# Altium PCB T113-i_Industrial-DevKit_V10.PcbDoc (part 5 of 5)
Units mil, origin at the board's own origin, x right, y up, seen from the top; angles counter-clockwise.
Board outline 4212.61 x 3188.98 mil, 4 copper layers (Top Layer, GND, PWR, Bottom Layer); 249 components, 236 nets, 911 pads, 571 vias.
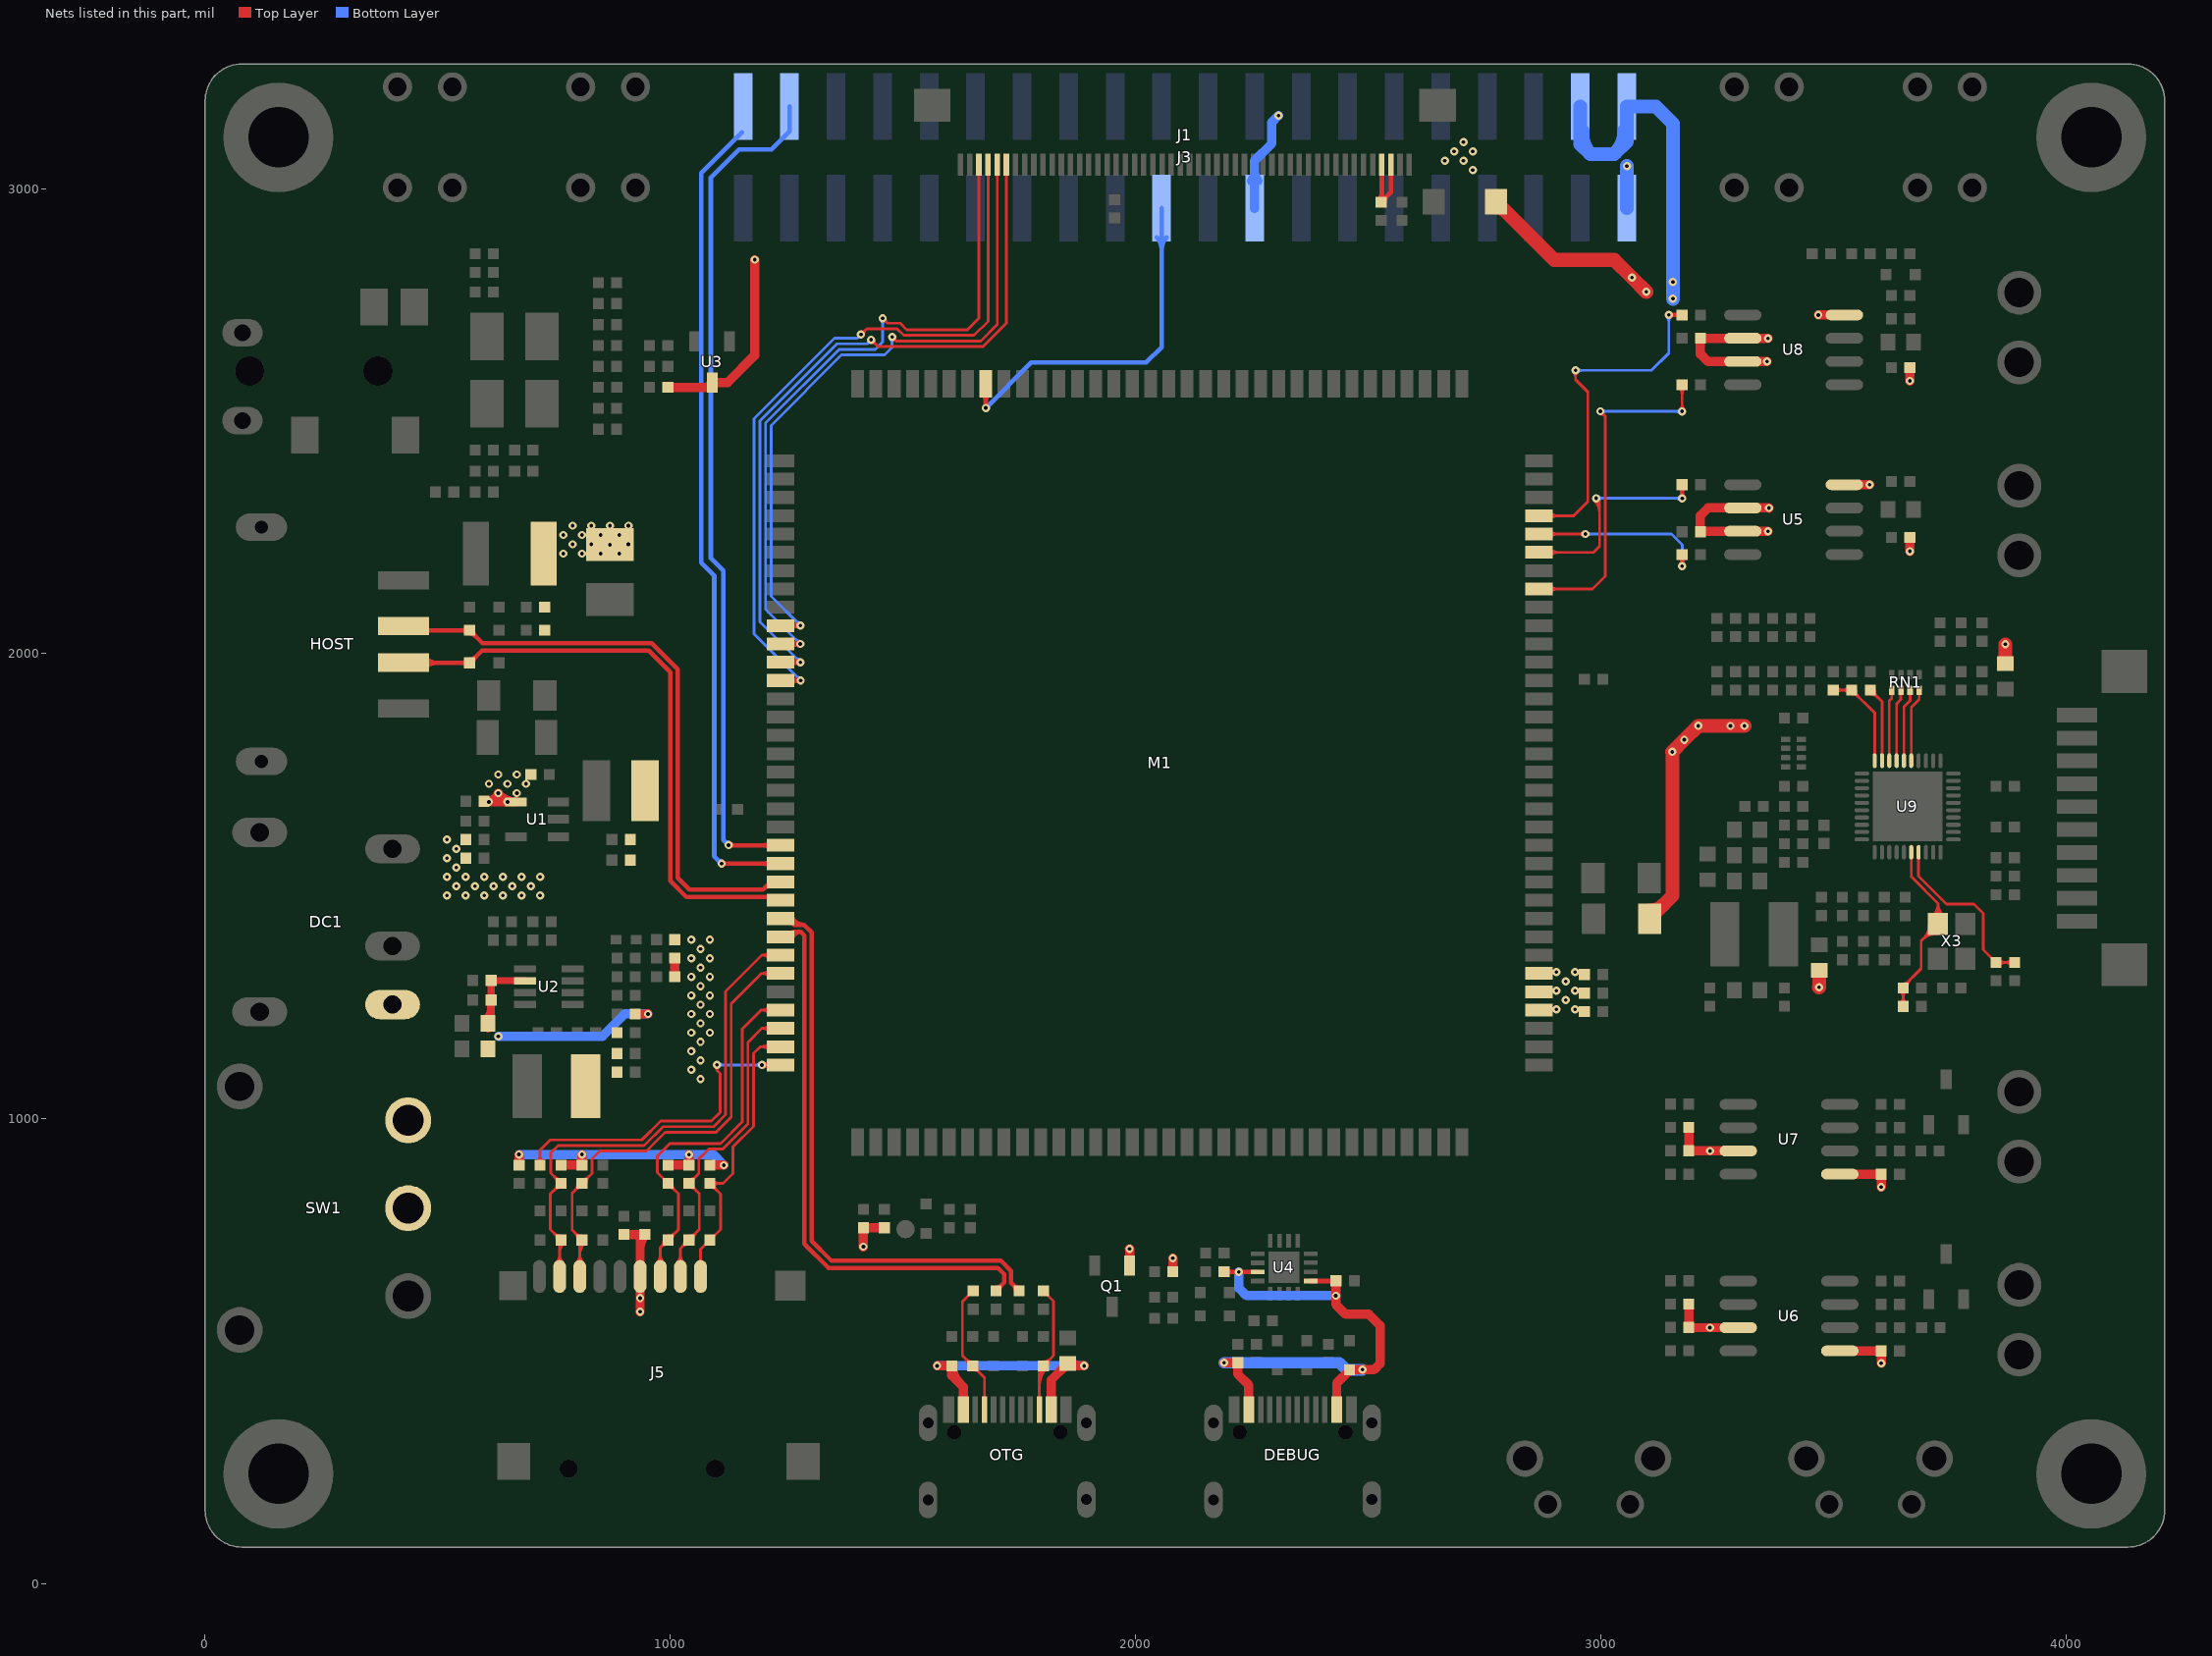
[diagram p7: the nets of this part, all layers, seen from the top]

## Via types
v1: diameter 17.72, hole 7.87, Top Layer to Bottom Layer, tented both sides, 571 vias

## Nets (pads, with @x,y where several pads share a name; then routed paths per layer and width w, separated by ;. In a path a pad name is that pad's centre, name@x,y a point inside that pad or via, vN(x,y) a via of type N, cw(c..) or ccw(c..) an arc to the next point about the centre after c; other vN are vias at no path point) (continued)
SD_CMD: D11.2 J5.3 M1.31 R34.2 | length 987.9
  Top Layer w6: J5.3@970.81,689.87 ccw(c952.4,708.27) 978.43,708.27 ccw(c1004.45,708.27) J5.3@986.05,689.87 ; J5.3@978.43,660.59 978.43,722.48 D11.2@995.04,739.09 1017.28,761.33 1017.28,838.67 R34.2@995.04,860.91 971.96,883.99 971.96,919.54 999.11,946.7 1108.01,946.7 1154.83,993.52 1154.83,1192.9 1195.4,1233.46 ; D11.2@986.23,739.09 cw(c964.96,739.09) 980,724.05 cw(c995.04,709.01) D11.2@995.04,730.28 ; D11.2@995.04,747.91 ccw(c995.04,769.18) 1010.08,754.14 ccw(c1025.12,739.09) D11.2@1003.85,739.09 ; R34.2@995.04,852.09 cw(c995.04,830.82) 1010.08,845.86 cw(c1025.12,860.91) R34.2@1003.85,860.91 ; M1.31@1213.83,1225.84 ccw(c1195.43,1207.44) 1195.43,1233.46 ; M1.31@1213.83,1241.09 cw(c1195.43,1259.49) 1195.43,1233.46 ; M1.31@1237.2,1233.46 1195.4,1233.46
SD_D0: D10.2 J5.7 M1.29 R33.2 | length 1224
  Top Layer w6: J5.7@797.58,689.87 ccw(c779.17,708.27) 805.2,708.27 ccw(c831.22,708.27) J5.7@812.82,689.87 ; D10.2@801.23,739.09 ccw(c779.96,739.09) 795,754.14 ccw(c810.04,769.18) D10.2@810.04,747.91 ; R33.2@801.23,860.91 cw(c779.96,860.91) 795,845.86 cw(c810.04,830.82) R33.2@810.04,852.09 ; J5.7@805.2,660.59 805.2,734.25 D10.2@810.04,739.09 788.78,760.35 788.78,839.65 R33.2@810.04,860.91 831.34,882.21 831.34,913.32 848.24,930.22 948.61,930.22 989.25,970.86 1098.23,970.86 1130.83,1003.46 1130.83,1247.18 1195.86,1312.2 ; 805.2,706.14 cw(c843,706.14) D10.2@816.27,732.86 ; 805.2,720.62 cw(c828.51,720.62) D10.2@812.03,737.11 ; R33.2@810.04,869.72 ccw(c810.04,890.99) 825.08,875.95 ccw(c840.12,860.91) R33.2@818.85,860.91 ; M1.29@1213.74,1304.67 ccw(c1195.86,1287.21) 1195.86,1312.2 ; M1.29@1213.74,1319.74 cw(c1195.86,1337.2) 1195.86,1312.2 ; M1.29@1237.2,1312.2 1195.86,1312.2
SD_D1: D9.2 J5.8 M1.28 R32.2 | length 1353.7
  Top Layer w6: J5.8@754.27,689.87 ccw(c735.86,708.27) 761.89,708.27 ccw(c787.91,708.27) J5.8@769.51,689.87 ; D9.2@756.23,739.09 ccw(c734.96,739.09) 750,754.14 ccw(c765.04,769.18) D9.2@765.04,747.91 ; D9.2@758.81,732.86 cw(c751.37,725.43) 761.89,725.43 ; J5.8@761.89,660.59 D9.2@761.89,735.94 ; 761.89,710.22 cw(c793.92,710.22) D9.2@771.27,732.86 ; 761.89,724.7 cw(c779.43,724.7) D9.2@767.03,737.11 ; R32.2@765.04,852.09 ccw(c765.04,830.82) 750,845.86 ccw(c734.96,860.91) 756.23,860.91 ccw(c734.96,860.91) 750,875.95 ccw(c765.04,890.99) R32.2@765.04,869.72 ; M1.28@1213.6,1344.2 ccw(c1196.55,1328.19) 1196.55,1351.57 ; M1.28@1213.6,1358.95 cw(c1196.55,1374.96) 1196.55,1351.57 ; M1.28@1237.2,1351.57 1196.55,1351.57 ; D9.2@761.89,735.94 D9.2@765.04,739.09 D9.2@761.89,742.24 ; D9.2@761.89,735.94 D9.2@761.89,742.24 ; D9.2@761.89,742.24 742.3,761.84 742.3,838.16 R32.2@765.04,860.91 743.22,882.73 743.22,926.91 758.53,942.22 943.64,942.22 984.36,982.94 1093.34,982.94 1118.83,1008.43 1118.83,1273.86 1196.55,1351.57
SD_D2: D8.2 J5.1 M1.33 R31.2 | length 734.7
  Top Layer w6: J5.1@1065.04,660.59 1065.04,719.09 D8.2@1085.04,739.09 1107.96,762.01 1107.96,837.99 R31.2@1085.04,860.91 1113.75,860.91 1134.65,881.8 1134.65,939.39 1178.83,983.58 1178.83,1140.23 1193.33,1154.72 M1.33@1237.2,1154.72 ; R31.2@1085.04,852.09 cw(c1085.04,830.82) 1100.08,845.86 cw(c1115.12,860.91) R31.2@1093.85,860.91 ; R31.2@1091.27,854.68 cw(c1106.31,839.63) 1106.31,860.91 cw(c1106.31,882.18) R31.2@1091.27,867.14 ; M1.33@1213.83,1147.1 ccw(c1195.43,1128.7) 1195.43,1154.72 ccw(c1195.43,1180.75) M1.33@1213.83,1162.35
SD_D3: D6.2 J5.2 M1.32 R30.2 | length 894.8
  Top Layer w6: J5.2@1014.11,689.87 ccw(c995.7,708.27) 1021.73,708.27 ccw(c1047.75,708.27) J5.2@1029.35,689.87 ; J5.2@1021.73,660.59 1021.73,720.78 D6.2@1040.04,739.09 1062.39,761.45 1062.39,838.55 R30.2@1040.04,860.91 1061.24,882.11 1061.24,913.1 1082.84,934.7 1112.98,934.7 1166.83,988.55 1166.83,1164.16 1196.77,1194.09 ; D6.2@1031.23,739.09 cw(c1009.96,739.09) 1025,724.05 cw(c1040.04,709.01) D6.2@1040.04,730.28 ; D6.2@1040.04,747.91 ccw(c1040.04,769.18) 1055.08,754.14 ccw(c1070.12,739.09) D6.2@1048.85,739.09 ; R30.2@1040.04,852.09 cw(c1040.04,830.82) 1055.08,845.86 cw(c1070.12,860.91) 1048.85,860.91 cw(c1070.12,860.91) 1055.08,875.95 cw(c1040.04,890.99) R30.2@1040.04,869.72 ; M1.32@1213.55,1186.77 ccw(c1196.77,1171.22) 1196.77,1194.09 ; M1.32@1213.55,1201.42 cw(c1196.77,1216.97) 1196.77,1194.09 ; M1.32@1237.2,1194.09 1196.77,1194.09
SD_DET: M1.34 R25.2 | length 886.4
  Top Layer w6: R25.2@713.81,906.51 ccw(c698.77,921.55) 720.04,921.55 ccw(c741.31,921.55) R25.2@726.27,906.51 ; R25.2@720.04,900.28 720.04,932.26 742.07,954.29 938.74,954.29 979.48,995.03 1088.46,995.03 1106.83,1013.4 1106.83,1096.96 1100.25,1103.55 ; v1@1096.63,1111 cw(c1090.77,1103.55) 1100.25,1103.55 ; v1(1100.25,1115.6) 1100.25,1103.55 ; v1@1103.87,1111 ccw(c1109.72,1103.55) 1100.25,1103.55 ; v1@1195.86,1115.49 v1@1195.99,1115.35 ; v1@1200.12,1110.53 cw(c1206.09,1101.06) 1208.99,1111.87 cw(c1211.52,1121.34) v1@1202.43,1117.68 ; v1@1200.45,1120.22 ccw(c1206.08,1127.96) 1208.55,1118.72 ccw(c1210.92,1109.88) v1@1202.43,1113.3 ; v1@1201.14,1111.35 cw(c1210.82,1101.67) M1.34@1210.82,1115.35 ; v1@1201.14,1119.63 ccw(c1211.47,1129.96) M1.34@1211.47,1115.35 ; M1.34@1213.72,1107.85 ccw(c1196,1090.67) v1@1196,1115.35 ; M1.34@1213.72,1122.86 cw(c1196,1140.03) v1@1196,1115.35 ; M1.34@1237.2,1115.35 v1@1195.99,1115.35
  Bottom Layer w6: v1(1100.25,1115.6) 1100.36,1115.49 v1@1195.86,1115.49 ; v1@1104.39,1111.46 cw(c1114.11,1101.74) 1114.11,1115.49 ; v1@1104.39,1119.75 ccw(c1114.67,1130.02) 1114.67,1115.49 ; v1@1192.86,1111.35 ccw(c1182.86,1101.35) 1182.86,1115.49 ccw(c1182.86,1129.63) v1@1192.86,1119.63
  other v1: 1197,1115.49
TP_X1: J1.46 M1.10 | length 1616.2
  Top Layer w6: M1.10@1237.2,2060.24 1279.61,2060.24 v1(1279.74,2060.37) ; M1.10@1260.57,2052.61 cw(c1278.98,2034.21) 1278.98,2060.24 cw(c1278.98,2086.26) M1.10@1260.57,2067.86 ; M1.10@1265.28,2060.24 ccw(c1265.28,2074.82) v1@1275.59,2064.51 ; M1.10@1265.9,2060.24 cw(c1265.9,2046.53) v1@1275.59,2056.22 ; M1.10@1266.09,2056.78 cw(c1269.68,2043.36) v1@1276.75,2055.32 ; M1.10@1266.22,2056.82 ccw(c1262.63,2070.24) v1@1274.66,2063.29 ; M1.10@1266.5,2063.58 ccw(c1269.67,2075.39) v1@1276.47,2065.23 ; 1266.74,2063.52 cw(c1263.36,2050.91) v1@1274.66,2057.44 ; v1(1476.87,2680.63) 1485.27,2672.24 ; v1@1477.63,2674.83 cw(c1478.83,2665.8) 1485.27,2672.24 ; v1@1482.68,2679.87 ccw(c1491.71,2678.68) 1485.27,2672.24 ; J1.46@1700.7,3031.25 cw(c1695.74,3026.29) 1702.75,3026.29 cw(c1709.77,3026.29) J1.46@1704.81,3031.25 ; J1.46@1702.75,3051.03 1702.75,2707.57 1667.42,2672.24 1485.27,2672.24
  Bottom Layer w6: v1@1273.88,2060.37 ccw(c1259.73,2060.37) 1269.73,2070.37 ccw(c1279.74,2080.37) v1@1279.74,2066.22 ; v1(1279.74,2060.37) 1216.62,2123.48 1216.62,2490.62 1368.14,2642.14 1460.48,2642.14 1476.87,2658.53 v1(1476.87,2680.63) ; v1@1472.73,2676.49 cw(c1462.73,2666.49) 1476.87,2666.49 cw(c1491.01,2666.49) v1@1481.01,2676.49
TP_X2: J1.45 M1.12 | length 1728.4
  Top Layer w6: M1.12@1237.2,1981.5 1279.45,1981.5 v1(1279.51,1981.44) ; M1.12@1260.57,1973.87 cw(c1278.98,1955.47) 1278.98,1981.5 cw(c1278.98,2007.52) M1.12@1260.57,1989.12 ; M1.12@1265.23,1981.5 cw(c1265.23,1967.17) v1@1275.36,1977.3 ; M1.12@1265.49,1981.5 ccw(c1265.49,1995.45) v1@1275.36,1985.58 ; v1@1274.42,1978.54 ccw(c1262.58,1971.77) 1266.11,1984.95 ccw(c1269.54,1997.74) v1@1276.45,1986.44 ; v1@1274.42,1984.36 cw(c1262.82,1991.02) 1266.28,1978.09 cw(c1269.53,1965.98) v1@1276.33,1976.52 ; v1@1431.85,2669.05 cw(c1431.85,2654.91) 1441.85,2664.91 cw(c1451.85,2674.91) v1@1437.71,2674.91 ; v1(1431.85,2674.91) 1446.52,2660.24 1672.39,2660.24 1722.44,2710.29 J1.45@1722.44,3051.03 ; J1.45@1720.39,3031.25 cw(c1715.43,3026.29) 1722.44,3026.29 cw(c1729.46,3026.29) J1.45@1724.5,3031.25
  Bottom Layer w6: v1@1273.65,1981.44 ccw(c1259.5,1981.44) 1269.5,1991.44 ccw(c1279.51,2001.44) v1@1279.51,1987.3 ; v1(1279.51,1981.44) 1192.34,2068.61 1192.34,2500.45 1358.03,2666.14 1423.09,2666.14 v1(1431.85,2674.91)
TP_Y1: J1.48 M1.11 | length 1662.8
  Top Layer w6: M1.11@1237.2,2020.87 v1@1279.26,2020.87 ; M1.11@1260.57,2013.24 cw(c1278.98,1994.84) 1278.98,2020.87 cw(c1278.98,2046.89) M1.11@1260.57,2028.49 ; M1.11@1265.08,2020.87 cw(c1265.08,2006.65) v1@1275.13,2016.7 ; M1.11@1265.18,2020.87 ccw(c1265.18,2034.94) v1@1275.13,2024.99 ; v1@1274.15,2018.01 ccw(c1262.66,2011.64) 1266.06,2024.33 ccw(c1269.4,2036.77) v1@1276.19,2025.82 ; v1@1274.15,2023.69 cw(c1262.75,2030.02) 1266.13,2017.42 cw(c1269.39,2005.24) v1@1276.14,2015.9 ; v1@1456.48,2715.1 cw(c1456.48,2700.95) 1466.48,2710.95 cw(c1476.48,2720.95) v1@1462.34,2720.95 ; v1(1456.48,2720.95) 1466.82,2710.62 1493.85,2710.62 1508.23,2696.24 1638.52,2696.24 1663.38,2721.1 J1.48@1663.38,3051.03 ; J1.48@1661.33,3031.25 cw(c1656.37,3026.29) 1663.38,3026.29 cw(c1670.4,3026.29) J1.48@1665.44,3031.25
  Bottom Layer w6: v1@1273.42,2020.85 ccw(c1259.27,2020.85) 1269.28,2030.85 ccw(c1279.28,2040.85) v1@1279.28,2026.7 ; v1(1279.28,2020.85) 1204.58,2095.54 1204.58,2495.63 1363.09,2654.14 1440.3,2654.14 1456.48,2670.33 v1(1456.48,2720.95) ; v1@1452.34,2716.81 cw(c1442.34,2706.81) 1456.48,2706.81 cw(c1470.62,2706.81) v1@1460.62,2716.81
TP_Y2: J1.47 M1.13 | length 1747.1
  Top Layer w6: M1.13@1237.2,1942.13 v1(1280.31,1942.15) ; M1.13@1260.57,1934.5 cw(c1278.98,1916.1) 1278.98,1942.13 cw(c1278.98,1968.15) M1.13@1260.57,1949.75 ; M1.13@1266.1,1942.13 ccw(c1266.1,1956.36) v1@1276.16,1946.29 ; M1.13@1266.23,1942.13 cw(c1266.23,1928.07) v1@1276.16,1938.01 ; M1.13@1266.5,1938.78 cw(c1270.01,1925.68) v1@1277.2,1937.18 ; M1.13@1266.58,1945.45 ccw(c1270.01,1958.24) v1@1277.15,1947.09 ; 1267.31,1939 ccw(c1263.93,1951.61) v1@1275.23,1945.08 ; 1267.41,1945.23 cw(c1264.08,1932.78) v1@1275.23,1939.22 ; v1(1409.86,2685.9) 1422.57,2698.62 1487.75,2698.62 1502.13,2684.24 1653.09,2684.24 1683.07,2714.22 J1.47@1683.07,3051.03 ; v1@1409.86,2691.76 ccw(c1409.86,2705.9) 1419.86,2695.9 ccw(c1429.86,2685.9) v1@1415.72,2685.9 ; J1.47@1681.02,3031.25 cw(c1676.06,3026.29) 1683.07,3026.29 cw(c1690.09,3026.29) J1.47@1685.13,3031.25
  Bottom Layer w6: v1@1274.45,1942.15 ccw(c1260.31,1942.15) 1270.31,1952.15 ccw(c1280.31,1962.15) v1@1280.31,1948.01 ; v1(1280.31,1942.15) 1180.08,2042.38 1180.08,2505.26 1352.96,2678.14 1402.1,2678.14 v1(1409.86,2685.9)
TVIN0: J3.40 M1.23 | length 1816.8
  Top Layer w10: v1(1110.22,1548.41) M1.23@1237.2,1548.43 ; v1@1112.95,1545.68 cw(c1119.59,1539.04) 1119.59,1548.43 ; v1@1112.95,1551.13 ccw(c1119.49,1557.67) 1119.49,1548.43 ; M1.23@1215.25,1542.22 ccw(c1200.26,1527.23) 1200.26,1548.43 ccw(c1200.26,1569.62) M1.23@1215.25,1554.63
  Bottom Layer w10: 1103.43,1555.08 ccw(c1110.22,1561.87) v1@1110.22,1552.26 ; 1103.72,1554.79 cw(c1097.34,1548.41) v1@1106.37,1548.41 ; v1(1110.22,1548.41) 1110.11,1548.41 1094.22,1564.29 1094.22,2167.65 1066.22,2195.65 1066.22,3032.98 J3.40@1154.19,3120.95
TVIN1: J3.38 M1.22 | length 1883.3
  Top Layer w10: v1@1125.27,1587.8 M1.22@1237.2,1587.8 ; v1@1128,1590.95 ccw(c1135.61,1598.56) 1135.61,1587.8 ; M1.22@1215.25,1581.59 ccw(c1200.26,1566.6) 1200.26,1587.8 ccw(c1200.26,1608.99) M1.22@1215.25,1594
  Bottom Layer w10: v1@1121.41,1588.22 ccw(c1112.1,1588.22) 1118.69,1594.81 ccw(c1125.27,1601.39) v1@1125.27,1592.08 ; v1(1125.27,1588.22) 1114.13,1599.36 1114.13,2178.31 1087.3,2205.15 1087.3,3024.04 1147.56,3084.31 1217.89,3084.31 1256.3,3122.72 J3.38@1256.3,3176.26
TVOUT0: J3.21 M1.129 | length 902.5
  Top Layer w10: M1.129@1671.94,2557.97 cw(c1656.95,2542.98) 1678.15,2542.98 cw(c1699.35,2542.98) M1.129@1684.36,2557.97 ; v1@1675.5,2530.91 ccw(c1669.12,2537.29) 1678.15,2537.29 ; 1678.15,2537.7 ccw(c1687.75,2537.7) v1@1680.96,2530.91 ; M1.129@1678.15,2579.92 1678.15,2528.27 v1(1678.23,2528.18)
  Bottom Layer w10: v1(1678.23,2528.18) 1775.93,2625.88 2023.14,2625.88 2056.3,2659.04 J3.21@2056.3,2957.75 ; v1@1678.23,2532.04 ccw(c1678.23,2541.35) 1684.82,2534.77 ccw(c1691.41,2528.18) v1@1682.09,2528.18 ; J3.21@2045.64,2895.32 cw(c2019.9,2869.58) 2056.3,2869.58 cw(c2092.7,2869.58) J3.21@2066.96,2895.32
TXC: C59.2 R73.1 U9.20 | length 312.5
  Top Layer w6: C59.2@3500,1921.57 R73.1@3540,1921.57 3589.1,1872.47 U9.20@3589.1,1769.66 ; C59.2@3506.23,1915.34 cw(c3521.27,1900.3) 3521.27,1921.57 cw(c3521.27,1942.85) C59.2@3506.23,1927.81 ; R73.1@3533.77,1915.34 ccw(c3518.73,1900.3) 3518.73,1921.57 ccw(c3518.73,1942.85) R73.1@3533.77,1927.81 ; R73.1@3540,1912.76 cw(c3540,1891.49) 3555.04,1906.53 cw(c3570.08,1921.57) R73.1@3548.81,1921.57
TXCTL: R74.1 U9.19 | length 195.6
  Top Layer w6: R74.1@3580,1912.76 cw(c3580,1891.49) 3595.04,1906.53 cw(c3610.08,1921.57) R74.1@3588.81,1921.57 ; R74.1@3580,1921.57 3604.9,1896.67 U9.19@3604.9,1769.66
TXD0: RN1.4 U9.18 | length 164.8
  Top Layer w6: U9.18@3620.6,1769.66 3620.6,1898 3625.94,1903.34 RN1.4@3625.94,1921.26 ; RN1.4@3623.89,1915.17 cw(c3618.93,1910.21) 3625.94,1910.21 cw(c3632.96,1910.21) RN1.4@3628,1915.17
TXD1: RN1.3 U9.17 | length 166.4
  Top Layer w6: U9.17@3636.4,1769.66 3636.4,1891.94 3645.63,1901.16 RN1.3@3645.63,1921.26 ; RN1.3@3643.57,1915.17 cw(c3638.61,1910.21) 3645.63,1910.21 cw(c3652.64,1910.21) RN1.3@3647.68,1915.17
TXD2: RN1.2 U9.16 | length 168.1
  Top Layer w6: U9.16@3652.1,1769.66 3652.1,1885.78 3665.32,1898.99 RN1.2@3665.32,1921.26 ; RN1.2@3663.26,1915.17 cw(c3658.3,1910.21) 3665.32,1910.21 cw(c3672.33,1910.21) RN1.2@3667.37,1915.17
TXD3: RN1.1 U9.15 | length 169.7
  Top Layer w6: U9.15@3667.9,1769.66 3667.9,1884.6 3685,1901.7 RN1.1@3685,1921.26 ; RN1.1@3682.95,1915.17 cw(c3677.99,1910.21) 3685,1910.21 cw(c3692.01,1910.21) RN1.1@3687.05,1915.17
TYPEC_CC1: D18.2 OTG.A5 R40.2 | length 362.5
  Top Layer w6: D18.2@1641.19,468.5 ccw(c1619.92,468.5) 1634.96,483.55 ccw(c1650,498.59) D18.2@1650,477.32 ; D18.2@1650,459.69 cw(c1650,438.42) 1665.04,453.46 cw(c1680.08,468.5) D18.2@1658.81,468.5 ; R40.2@1651,629.69 1628,606.69 1628,490.5 D18.2@1650,468.5 1675.35,443.15 OTG.A5@1675.35,374.13 ; OTG.A5@1673.3,398.63 ccw(c1668.34,403.59) 1675.35,403.59 ccw(c1682.37,403.59) OTG.A5@1677.41,398.63
TYPEC_CC2: D22.2 OTG.B5 R41.2 | length 406.4
  Top Layer w6: OTG.B5@1791.41,398.63 ccw(c1786.45,403.59) 1793.46,403.59 ccw(c1800.48,403.59) OTG.B5@1795.52,398.63 ; OTG.B5@1793.46,374.13 1793.46,459.97 D22.2@1802,468.5 1824,490.5 1824,607.69 R41.2@1802,629.69 ; 1793.46,426.63 cw(c1843.88,426.63) D22.2@1808.23,462.27 ; 1793.46,441.11 cw(c1829.39,441.11) D22.2@1803.99,466.52 ; 1793.46,455.6 cw(c1814.91,455.6) D22.2@1799.75,470.76 ; D22.2@1802,477.32 ccw(c1802,498.59) 1817.04,483.55 ccw(c1832.08,468.5) D22.2@1810.81,468.5
UART2_RXD: M1.97 R44.1 | length 695.9
  Top Layer w6: M1.97@2867.13,2217.72 2984.81,2217.72 2997.75,2230.66 2997.75,2326.73 ; M1.97@2890.5,2210.09 cw(c2908.9,2191.69) 2908.9,2217.72 cw(c2908.9,2243.74) M1.97@2890.5,2225.34 ; v1@2986.29,2329.9 cw(c2958.64,2302.24) 2997.75,2302.24 ; v1(2990.44,2334.04) 2997.75,2326.73 ; v1@2990.54,2334.14 cw(c2973.12,2316.73) 2997.75,2316.73 ; v1@2991.86,2328.36 cw(c2993.37,2322.34) 2997.75,2326.73 ; v1@2996.12,2332.62 ccw(c3002.14,2331.11) 2997.75,2326.73 ; R44.1@3169.08,2356.92 cw(c3154.04,2341.88) 3175.32,2341.88 cw(c3196.59,2341.88) R44.1@3181.55,2356.92 ; v1@3170.88,2337.58 ccw(c3160.54,2345.86) 3173.33,2349.29 ; v1@3171.31,2338.06 ccw(c3161.63,2347.74) 3175.32,2347.74 ; v1@3172.52,2339 ccw(c3169.19,2344.77) 3175.63,2343.04 ; 3174.86,2343.58 ccw(c3182.16,2345.54) v1@3178.38,2339 ; 3175.32,2348.39 ccw(c3189.92,2348.39) v1@3179.59,2338.06 ; R44.1@3175.32,2363.15 3175.32,2334.06 v1(3175.45,2333.92) ; 3177.18,2348.85 ccw(c3188.68,2345.77) v1@3179.81,2337.83
  Bottom Layer w6: v1@2990.44,2333.92 v1(3175.45,2333.92) ; v1@2994.58,2329.9 cw(c3004.29,2320.19) 3004.29,2333.92 ; v1@2994.58,2338.18 ccw(c3004.87,2348.47) 3004.87,2333.92 ; v1@3171.31,2329.78 ccw(c3161.31,2319.78) 3161.31,2333.92 ccw(c3161.31,2348.06) v1@3171.31,2338.06
UART2_TXD: M1.98 R43.1 | length 591.6
  Top Layer w6: M1.98@2867.13,2257.09 v1@2967.09,2257.09 ; M1.98@2890.5,2249.46 cw(c2908.9,2231.06) 2908.9,2257.09 cw(c2908.9,2283.11) M1.98@2890.5,2264.71 ; 2952.58,2257.09 ccw(c2952.58,2271.75) v1@2962.95,2261.38 ; 2953.31,2257.09 cw(c2953.31,2243.46) v1@2962.95,2253.1 ; R43.1@3169.08,2206.92 cw(c3154,2191.84) v1@3175.33,2191.84 ; v1@3170.88,2191.8 ccw(c3163.31,2198.26) 3172.92,2200.84 ; v1@3171.19,2192.14 ccw(c3161.19,2202.14) 3175.33,2202.14 ccw(c3189.47,2202.14) v1@3179.47,2192.14 ; v1@3172.4,2193.07 ccw(c3167.06,2202.32) 3177.38,2199.56 ; 3173.25,2199.6 ccw(c3183.64,2202.38) v1@3178.26,2193.07 ; v1@3175.33,2186.36 R43.1@3175.32,2213.15 ; v1@3175.33,2191.92 cw(c3196.55,2191.92) R43.1@3181.55,2206.92 ; 3177.72,2200.83 ccw(c3187.27,2198.27) v1@3179.77,2191.82
  Bottom Layer w6: v1(2967.09,2257.24) 2967.21,2257.12 3152.44,2257.12 3175.33,2234.23 v1@3175.33,2186.36 ; v1@2971.23,2253.1 cw(c2980.95,2243.38) 2980.95,2257.12 ; v1@2971.23,2261.38 ccw(c2981.52,2271.67) 2981.52,2257.12 ; v1@3171.19,2192.14 ccw(c3161.19,2202.14) 3175.33,2202.14 ccw(c3189.47,2202.14) v1@3179.47,2192.14
  other v1: 3175.33,2188
UART3_RXD: M1.99 R59.1 | length 924.5
  Top Layer w6: M1.99@2878.79,2296.46 2941.95,2296.46 2972.42,2326.93 2972.42,2562.55 2946.05,2588.92 v1(2946.05,2609.01) ; M1.99@2890.5,2288.83 cw(c2908.9,2270.43) 2908.9,2296.46 cw(c2908.9,2322.48) M1.99@2890.5,2304.08 ; v1@2941.91,2604.87 cw(c2931.91,2594.87) 2946.05,2594.87 cw(c2960.19,2594.87) v1@2950.19,2604.87 ; v1(3146.65,2728.13) R59.1@3175.32,2728.15 ; v1@3150.45,2723.67 cw(c3158.32,2714.41) 3161.47,2726.15 ; v1@3150.43,2732.6 ccw(c3158.32,2741.95) 3161.48,2730.14 ; v1@3150.79,2723.98 cw(c3160.79,2713.98) 3160.79,2728.13 cw(c3160.79,2742.27) v1@3150.79,2732.27 ; v1@3151.72,2725.2 cw(c3158.35,2721.37) 3156.37,2728.77 ; v1@3151.72,2731.06 ccw(c3158.27,2734.84) 3156.31,2727.53 ; v1@3153.99,2728.13 ccw(c3153.99,2749.48) R59.1@3169.08,2734.38 ; v1@3154.1,2728.13 cw(c3154.1,2706.93) R59.1@3169.08,2721.92
  Bottom Layer w6: v1(2946.05,2609.01) 3109.43,2609.01 3146.65,2646.23 v1(3146.65,2728.13) ; v1@2950.19,2604.87 cw(c2960.2,2594.87) 2960.2,2609.01 cw(c2960.19,2623.15) v1@2950.19,2613.15 ; v1@3142.51,2723.98 cw(c3132.51,2713.98) 3146.65,2713.98 cw(c3160.79,2713.98) v1@3150.79,2723.98
UART3_TXD: M1.95 R58.1 | length 909.5
  Top Layer w6: M1.95@2867.13,2138.98 2982.64,2138.98 3009.75,2166.09 3009.75,2510.51 v1(2999.32,2520.94) ; M1.95@2890.5,2131.35 cw(c2908.9,2112.95) 2908.9,2138.98 cw(c2908.9,2165) M1.95@2890.5,2146.6 ; v1@2999.32,2515.08 cw(c2999.32,2500.94) 3009.32,2510.94 cw(c3019.32,2520.94) v1@3005.17,2520.94 ; R58.1@3169.08,2571.92 cw(c3154.29,2557.12) 3175.21,2557.12 ; v1@3171.07,2524.97 ccw(c3161.07,2534.97) 3175.21,2534.97 ccw(c3189.36,2534.97) v1@3179.36,2524.97 ; v1(3175.21,2520.83) 3175.21,2578.05 R58.1@3175.32,2578.15 ; 3175.21,2556.63 cw(c3196.83,2556.63) R58.1@3181.55,2571.92
  Bottom Layer w6: v1(2999.32,2520.94) 3175.1,2520.94 v1(3175.21,2520.83) ; v1@3003.46,2516.8 cw(c3013.46,2506.8) 3013.46,2520.94 cw(c3013.46,2535.08) v1@3003.46,2525.08 ; 3160.8,2520.94 cw(c3160.8,2506.42) v1@3171.07,2516.69 ; 3161.34,2520.94 ccw(c3161.34,2534.71) v1@3171.07,2524.97
USB0_DM: M1.26 R39.2 | length 1332.7
  Top Layer w9.53: M1.26@1237.2,1430.32 1252.79,1430.32 1266.05,1417.06 1287.08,1417.06 ; M1.26@1252.48,1430.11 ccw(c1272.48,1438.9) 1272.48,1417.06 ; M1.26@1261.2,1433.94 ccw(c1287.08,1445.32) 1287.08,1417.06 ; R39.2@1742.95,629.69 ccw(c1725.94,629.69) 1737.97,641.71 ccw(c1750,653.74) R39.2@1750,636.73 ; R39.2@1750,629.69 1732.71,646.97 1732.71,672.62 1710.24,695.09 1345.67,695.09 1303.73,737.03 1303.73,1400.4 1287.08,1417.06
USB0_DP: M1.27 R38.2 | length 1313
  Top Layer w9.53: M1.27@1237.2,1390.94 1257.3,1390.94 1267.88,1401.53 ; M1.27@1252.46,1391.11 cw(c1267.06,1386.09) 1267.06,1401.53 ; M1.27@1256.42,1399.26 ccw(c1260.46,1408.95) 1267.88,1401.53 ; M1.27@1261.48,1388.01 cw(c1280.42,1381.49) 1280.42,1401.53 ; M1.27@1261.97,1390.94 cw(c1273.23,1390.94) M1.27@1265.27,1398.91 ; R38.2@1700,629.69 1717.18,646.87 1717.18,666.19 1704.08,679.29 1339.52,679.29 1288.2,730.6 1288.2,1393.75 1280.42,1401.53 ; R38.2@1700,636.73 ccw(c1700,653.74) 1712.03,641.71 ccw(c1724.06,629.69) R38.2@1707.05,629.69 ; 1267.88,1401.53 1280.42,1401.53
USB1_DM: D19.2 HOST.2 M1.24 | length 1392.2
  Top Layer w9.53: HOST.2@426.62,2059.37 435.99,2050 D19.2@568.5,2050 596.24,2022.27 959.84,2022.27 1015.74,1966.37 1015.74,1517.68 1040.89,1492.53 1198.84,1492.53 ; D19.2@563.52,2045.02 ccw(c551.49,2032.99) 551.49,2050 ccw(c551.49,2067.01) D19.2@563.52,2054.98 ; D19.2@568.5,2042.95 cw(c568.5,2025.94) 580.53,2037.97 cw(c592.56,2050) D19.2@575.55,2050 ; M1.24@1220.45,1500.1 ccw(c1217.51,1473.86) 1198.84,1492.53 ; M1.24@1237.2,1509.06 1215.37,1509.06 1198.84,1492.53
USB1_DP: D20.2 HOST.3 M1.25 | length 1417
  Top Layer w9.53: HOST.3@426.62,1980.62 427.24,1980 D20.2@568.5,1980 595.12,2006.62 953.34,2006.62 999.98,1959.98 999.98,1511.48 1034.46,1477 1229.89,1477 M1.25@1237.2,1469.69 ; HOST.3@472.6,1970.07 cw(c496.56,1946.11) 496.56,1980 ; HOST.3@472.6,1991.18 ccw(c499.58,2018.15) 499.58,1980 ; D20.2@563.52,1975.02 ccw(c551.49,1962.99) 551.49,1980 ccw(c551.49,1997.01) D20.2@563.52,1984.98 ; D20.2@568.5,1987.05 ccw(c568.5,2004.06) 580.53,1992.03 ccw(c592.56,1980) D20.2@575.55,1980
USB_OTG_VBUS: C40.2 D15.2 OTG.A4B9 OTG.B4A9 | length 685.9
  Top Layer w20: v1(1573.65,468.5) D15.2@1605,468.5 1605,448 1630.08,422.92 OTG.A4B9@1630.08,374.13 ; D15.2@1606.81,468.5 ccw(c1660.68,468.5) 1622.59,430.41 ; OTG.B4A9@1819.06,374.13 1819.06,438.31 C40.2@1854.41,473.66 1859.56,468.51 v1(1889.92,468.51) ; C40.2@1841.24,460.49 ccw(c1828.06,473.66) C40.2@1846.69,473.66 ; C40.2@1860.44,477.73 ccw(c1882.69,499.97) v1@1882.69,468.51
  Bottom Layer w20: v1(1573.65,468.5) v1(1889.92,468.51)
VBUS: C33.2 C34.1 C36.1 D3.2 DEBUG.A4B9 DEBUG.B4A9 U4.3 U4.9 | length 1316.8
  Top Layer w10: C36.1@2190.35,671.22 2191.17,670.41 v1(2221.99,670.41) U4.3@2262.35,670.41 ; C36.1@2195.17,666.4 cw(c2204.84,656.74) 2204.84,670.41 ; C36.1@2195.17,676.04 ccw(c2208.76,689.62) 2208.76,670.41 ; v1@2219.27,667.68 ccw(c2212.68,661.09) 2212.68,670.41 ccw(c2212.68,679.72) v1@2219.27,673.14 ; v1@2224.72,667.68 cw(c2231.31,661.09) 2231.31,670.41 cw(c2231.31,679.72) v1@2224.72,673.14 ; U4.9@2376.52,650.79 2430.55,650.79 C33.2@2430.8,651.04 ; 2413.5,650.79 ccw(c2413.5,668.7) C33.2@2426.17,656.04 ; 2415.58,650.79 cw(c2415.58,635.82) C33.2@2426.17,646.4
  Top Layer w20: v1(2190.38,475.15) 2190.54,475.32 C34.1@2220,475.32 2220,450.68 2243.71,426.97 DEBUG.A4B9@2243.71,374.13 ; C33.2@2430.98,651.22 2430.8,651.04 v1(2430.8,619.24) 2430.8,600.36 2451.78,579.39 2501.72,579.39 2526,555.11 2526,473.55 2512.6,460.15 v1(2488.09,460.15) 2461.64,460.15 2432.68,431.19 DEBUG.B4A9@2432.68,374.13
  Bottom Layer w20: v1(2221.99,670.41) 2221.99,635.98 2238.72,619.25 v1(2430.8,619.24)
  Bottom Layer w25: v1(2190.38,475.15) 2438.47,475.15 2453.47,460.15 v1(2488.09,460.15)
VCC33_EPHY: C1.2 C6.2 C10.2 C11.2 C13.1 C35.1 C37.1 C50.2 C51.2 J1.3 J1.4 J3.1 J3.17 J5.4 L1.2 Q1.1 R3.1 R29.1 R30.1 R31.1 R32.1 R33.1 R34.1 R37.1 R63.2 R64.2 R65.2 R77.2 R78.2 U3.3 U6.5 U7.5 | length 2925.9
  Top Layer w10: C1.2@2523.2,2975.43 ccw(c2507.93,2990.7) 2529.52,2990.7 ; C1.2@2528.02,2970.61 C1.2@2529.52,2972.12 ; C1.2@2528.02,2977.42 ccw(c2528.02,2993.87) 2539.64,2982.24 ccw(c2551.27,2970.61) C1.2@2534.83,2970.61 ; 2529.52,2983.42 ccw(c2540.82,2983.42) C1.2@2532.83,2975.43 ; J1.4@2529.52,3051.03 C1.2@2529.52,2972.12 ; J1.3@2549.21,3051.03 2549.21,2991.81 C1.2@2529.52,2972.12
  Top Layer w20: v1(674.64,923) 674.64,900.67 R29.1@675.04,900.28 ; R32.1@765.04,900.28 R33.1@810.04,900.28 v1(810.04,923) ; C35.1@900.04,750.91 C37.1@945.04,750.91 935.12,740.99 J5.4@935.12,660.59 v1(935.1,614.07) v1(935.1,584.74) v1@934.96,584.6 ; 935.12,722.58 cw(c973.36,722.58) C37.1@946.32,749.62 ; C13.1@994.68,2572.52 1079.29,2572.52 U3.3@1090,2583.23 1123.35,2583.23 1181.3,2641.17 v1(1181.3,2847.08) ; R34.1@995.04,900.28 R30.1@1040.04,900.28 1039.9,900.41 v1(1039.9,922.92) ; R31.1@1085.04,900.28 1114.8,900.28 v1(1115.09,899.98) ; v1(1415.11,724.71) 1415,724.82 R64.2@1415,765.31 R63.2@1460,765.31 ; v1(1987.24,719.87) 1987.4,719.71 Q1.1@1987.4,684.29 ; v1(2080.23,700.08) 2080.35,699.95 R37.1@2080.35,671.22 ; U6.5@3514.15,500.63 C50.2@3603.39,500.63 3603.39,474.23 v1(3603.26,474.1) ; U7.5@3514.15,880.63 C51.2@3603.39,880.63 3603.39,853.14 v1(3603.12,852.86)
  Top Layer w30: R65.2@3105.24,1430 3154.29,1479.06 3154.29,1788.53 v1(3154.01,1788.81) v1(3179.92,1814.73) v1(3209.83,1844.63) 3279.03,1844.63 v1(3279.17,1844.49) v1(3309.07,1844.49) v1@3309.22,1844.34 ; R65.2@3105.24,1447.48 ccw(c3105.24,1489.68) 3135.08,1459.84 ; v1(3469.69,1282.46) 3470,1282.77 R77.2@3470,1318.7 ; R78.2@3870,1978.82 v1(3870,2020)
  Bottom Layer w20: v1(674.64,923) v1(810.04,923) 1092.07,923 v1(1115.09,899.98) ; J3.17@2249.17,3016.65 ccw(c2231.97,3033.85) 2256.3,3033.85 ccw(c2280.63,3033.85) J3.17@2263.43,3016.65 ; J3.17@2256.3,2957.75 2256.3,3059.95 2293.01,3096.67 2293.01,3142.49 v1(2307.68,3157.15)
  Bottom Layer w30: J3.1@3056.3,2957.75 3056.3,3048.11 v1(3056.6,3048.41)
  other v1: 520,1480 560,1480 600,1480 640,1480 680,1480 720,1480 540,1500 580,1500 620,1500 660,1500 700,1500 520,1520 560,1520 600,1520 640,1520 680,1520 720,1520 540,1540 520,1560 540,1580 520,1600 2725.15,3039.85 2665,3060 2705.15,3059.85 2685.15,3079.85 2725.15,3079.85 2705.15,3099.85
VCC_5V: C3.2 C17.1 C18.1 C19.1 C20.1 C41.1 C42.2 C43.1 C45.1 C46.1 C47.1 C48.1 C49.2 C54.2 C55.2 C56.2 C57.2 D1.1 F1.1 J3.2 J3.4 L2.2 M1.72 M1.73 M1.74 R1.2 R11.1 R12.2 R51.1 R60.1 U1.4 U5.2 U5.3 U5.8 U6.3 U7.3 U8.2 U8.3 U8.8 | length 2637.8
  Top Layer w20: C3.2@599.69,1682.52 601.05,1681.16 U1.4@668.23,1681.16 cw(c668.23,1732.44) v1@629.13,1699.26 ; C3.2@601.05,1681.16 ccw(c601.05,1714.83) v1@631.02,1699.48 ; C17.1@1009.68,1305 R11.1@1009.68,1345 ; C45.1@3189.68,601.26 C47.1@3189.68,551.26 3190.31,550.63 v1(3234.89,550.63) U6.3@3295.85,550.63 ; C48.1@3189.68,981.26 C46.1@3189.68,931.26 3190.31,930.63 v1(3235.16,930.63) U7.3@3295.85,930.63 ; C49.2@3214.69,2262 3214.69,2296.69 3231.15,2313.15 U5.2@3305.85,2313.15 3361.85,2313.15 v1(3362,2313) ; C54.2@3214.69,2678.15 3214.69,2644.31 3230.85,2628.15 U8.3@3305.85,2628.15 3357.85,2628.15 v1(3358,2628) ; C49.2@3215.24,2263.15 U5.3@3305.85,2263.15 3359.85,2263.15 v1(3360,2263) ; C54.2@3215.24,2678.15 U8.2@3305.85,2678.15 3359.85,2678.15 v1(3360,2678) ; v1(3468,2728) 3468.15,2728.15 U8.8@3524.15,2728.15 ; U5.8@3524.15,2363.15 3577.98,2363.15 v1(3578.05,2363.22) ; R51.1@3664.68,2250 3664.68,2220.32 v1(3665,2220) ; R60.1@3664.68,2615 3664.68,2586.58 v1(3664.91,2586.35)
  Top Layer w30: D1.1@2775.2,2959.13 cw(c2775.2,2928.81) D1.1@2796.64,2950.25 ; D1.1@2775.2,2971.69 2900.1,2846.79 3029.27,2846.79 v1(3067.72,2808.34) v1(3098.19,2777.87) v1@3098.19,2777.59
  Bottom Layer w30: J3.4@2956.3,3176.26 2956.3,3095.74 2978.28,3073.76 ; J3.4@2961.33,3123.82 ccw(c3020.45,3115.93) 2978.28,3073.76 ; 3031.07,3075.85 ccw(c2982.44,3124.49) J3.2@3051.22,3124.49 ; v1@3155.57,2763.05 v1(3155.43,2763.19) v1(3155.43,2799.09) 3155.43,3139.25 3118.42,3176.26 J3.2@3056.3,3176.26 3056.3,3101.08 3028.99,3073.76 2978.28,3073.76
  other v1: 1065,1085 1045,1105 1065,1125 1045,1145 1065,1165 1045,1185 1085,1185 1065,1205 1045,1225 1085,1225 2905,1235 2945,1235 1065,1245 2925,1255 1045,1265 1085,1265 2905,1275 2945,1275 1065,1285 2925,1295 1045,1305 1085,1305 2905,1315 2945,1315 1065,1325 1045,1345 1085,1345 1065,1365 1045,1385 1085,1385 610,1681.16 650,1681.16 630,1700 670,1700 610,1720 650,1720 690,1720 630,1740 670,1740 770,2215 810,2215 850,2215 890,2215 790,2235 830,2235 870,2234.1 910,2235 770,2255 810,2255 850,2255 890,2255 790,2275 830,2275 870,2275 910,2275
VIN: DC1.1 SW1.3
VIN_12V: C4.1 C5.1 C7.1 C9.1 R7.1 SW1.2 U2.2 | length 611.6
  Top Layer w15: C7.1@601.73,1212.8 ccw(c570.44,1244.08) C4.1@614.68,1244.08 ; C7.1@607.56,1192.48 614.68,1199.61 C9.1@614.68,1297.48 615.65,1296.51 U2.2@687.9,1296.51 ; C4.1@610.95,1252.84 cw(c593.58,1242.82) 612.95,1237.63 ; C9.1@617.73,1300.53 ccw(c627.43,1310.23) 627.43,1296.51
  Top Layer w20: R7.1@924.68,1225 951.81,1225 v1(951.9,1225.09)
  Bottom Layer w20: v1(630.26,1177.1) 853.92,1177.1 901.91,1225.09 v1(951.9,1225.09)
XTAL_IN: C60.1 R79.1 U9.36 X3.1 | length 697.6
  Top Layer w6: C60.1@3644.08,1247.49 ccw(c3629.04,1262.53) 3650.32,1262.53 ccw(c3671.59,1262.53) C60.1@3656.55,1247.49 ; R79.1@3644.08,1275.03 cw(c3629.04,1259.99) 3650.32,1259.99 cw(c3671.59,1259.99) R79.1@3656.55,1275.03 ; C60.1@3650.32,1241.26 R79.1@3650.32,1281.26 3650.32,1283.84 3689.18,1322.71 3689.18,1382.37 X3.1@3725.47,1418.66 ; R79.1@3650.32,1290.07 ccw(c3650.32,1305.11) 3660.95,1294.48 ; R79.1@3659.13,1281.26 cw(c3686.63,1281.26) 3667.18,1300.71 ; U9.36@3667.9,1572.86 3667.9,1520.18 3725.47,1462.61 ; 3690.27,1383.46 cw(c3725.47,1348.25) X3.1@3725.47,1398.04 ; 3695.02,1388.21 ccw(c3666.54,1416.69) X3.1@3706.82,1416.69 ; 3700.51,1393.7 cw(c3725.47,1368.74) X3.1@3725.47,1404.04 ; X3.1@3705.26,1398.45 ccw(c3687.02,1416.69) X3.1@3712.82,1416.69 ; X3.1@3712.97,1434.47 ccw(c3687.56,1462.61) 3725.47,1462.61 ; X3.1@3716.99,1430.02 ccw(c3699.76,1449.1) 3725.47,1449.1 ccw(c3751.18,1449.1) X3.1@3733.95,1430.02 ; X3.1@3725.47,1432.99 3725.47,1462.61 ; X3.1@3737.97,1434.47 cw(c3763.38,1462.61) 3725.47,1462.61
XTAL_OUT: R80.1 R89.2 U9.37 | length 447.4
  Top Layer w6: U9.37@3683.6,1572.86 3683.6,1521.45 3743.41,1461.64 3802.73,1461.64 3822.9,1441.47 3822.9,1363.05 R89.2@3850,1335.94 R80.1@3890,1335.94 ; R89.2@3856.23,1329.71 cw(c3871.27,1314.67) 3871.27,1335.94 cw(c3871.27,1357.22) R89.2@3856.23,1342.18 ; R80.1@3883.77,1329.71 ccw(c3868.73,1314.67) 3868.73,1335.94 ccw(c3868.73,1357.22) R80.1@3883.77,1342.18
pads on no net: CN1. CN1.6 DC1.4 DC1.5 DEBUG. DEBUG.A8 DEBUG.B8 J1.34 J1.49 J5.14 J5.15 OTG. OTG.A8 OTG.B8 SW1.1 U4.10 U4.11 U4.12 U4.13 U4.14 U4.15 U4.16

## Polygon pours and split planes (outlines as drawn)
VCC33_EPHY on PWR "PWR_VCC33_EPHY" (solid, remove dead copper, pour order 10): -5,3270 35,3270 4215,3270 4215,3265 4215,75 4195,75 -5,75 -5,85 -5,3270
VCC_5V on PWR "PWR_VCC_5V" (solid, remove dead copper, pour order 9): 585,2840 3688.49,2840 3698.49,2830 3700,2828.49 3700,2819.26 3700,2165 3694.18,2159.18 3685,2150 3660,2150 3355,2150 3330,2125 3230,2025 3230,1996.51 3230,1231.63 3283.76,1177.87 3365,1096.63 3365,980.49 3365,521.51 3363.49,520 3358.49,515 3335,515 2620,515 2550,585 2380,755 2330,755 950,755 890,815 845,860 845,971.18 845,1580 813.04,1611.96 795,1630 695,1630 575.5,1630 570.25,1635.25 570,1635.5 570,1645 570,2835 575,2840 585,2840
GND on GND "GND_GND" (solid, remove dead copper, pour order 8): -5,3270 35,3270 4215,3270 4215,3265 4215,75 4195,75 -5,75 -5,85 -5,3270
GND on Top Layer "TOP_GND" (solid, remove dead copper, pour order 7): -5,3270 35,3270 4215,3270 4215,3265 4215,75 4195,75 -5,75 -5,85 -5,3270
GND on Bottom Layer "BOTTOM_GND" (solid, remove dead copper, pour order 6): -5,3270 35,3270 4215,3270 4215,3265 4215,75 4195,75 -5,75 -5,85 -5,3270

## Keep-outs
Keep-Out Layer:
  the board outline again, w11.81

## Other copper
Top Layer:
  region net NetC12_1: 647.01,1436.01 647,1436 647,1349 664,1332 664,1314 713,1314 717,1318 717,1396 676,1396 671,1401 671,1436
  region net NetC14_2: 721,1197 728,1190 728,1001 660,1001 660,1193 664,1197
  region net VCC_5V: 898,1197 898,1001 786,1001 786,1142 861,1142 871,1152 871,1197
  region net VIN_12V: 645,1310 653,1302 653,1290 645,1282 645,773 626,754 394,754 382,766 382,849 393,860 537,860 591,914 591,1222 602,1233 602,1310
  region net VCC_5V: 587.01,1686.01 587.01,1748.01 591,1752 713,1752 713,1725 692,1704 692,1670 587,1670
  region net NetL1_1: 736,1691 791,1691 795,1695 795,1770 796,1771 871,1771 871,1639 811,1639 811,1669 809,1671 736,1671
  region net NetD21_2: 371,2138.01 371.01,2138 533,2138 549,2122 549,2088 582,2088 582,2127 588,2133 611,2133 611,2284 393,2284 371,2262
  region net VCC_5V: 700,2285 922,2285 922,2198 776,2198 763,2185 763,2048 753,2038 717,2038 717,2114 700,2131
  region net GND: 351,1436 342,1427 342,1343 347,1338 493,1338 534,1297 534,1132 569,1132 569,1219 588,1238 588,1352 597,1361 632,1361 632,1436
  region net REGOUT: 3360.01,1466.01 3394.01,1466.01 3533,1605 3576,1605 3577,1604 3577,1597 3576,1596 3561,1596 3432,1467 3432,1327 3361,1327 3361,1466
  region net REGOUT: 3361,1327 3361,1305 3354,1298 3326,1298 3326,1258 3363,1258 3374,1269 3422,1269 3432,1279 3432,1327
  region net NetC71_1: 3271,1585 3304,1585 3304,1258 3271,1258 3271,1267 3269,1269 3214,1269 3212,1271 3212,1530 3266,1530 3271,1535
  region net VIN: 477,1280 488,1269 488,955 478,945 369,945 341,973 341,1276 345,1280
  region net VCC_5V: 2977,1326 2978,1325 2978,1218 2837,1218 2837,1326
  region net NetC6_1: 587,1652 620,1652 624,1648 624,1621 629,1616 692,1616 692,1562 678,1548 587,1548
  region net VCC33_EPHY: 915,1771 977,1771 977,1483 959,1465 521,1465 511,1475 511,1611 512,1612 573,1612 573,1540 579,1534 898,1534 901,1537 901,1613 915,1627
  region net GND: 735,1654 786,1654 819,1621 885,1621 887,1619 887,1544 805,1544 797,1552 797,1614 778,1633 735,1633
  region net VCC33_EPHY: 2523,3105 2527,3109 2735,3109 2735,3020 2624,3020 2618,3026 2618,3073 2610,3081 2557,3081 2555,3079 2555,2990 2541,2976 2541,2958 2516,2958 2516,2992 2523,2999
  region net GND: 658.01,1254.01 658.02,1254 729,1254 732,1251 732,1233 705,1206 654,1206 654,1254
  region net GND: 912,1277 981,1277 1009,1249 1009,1103 994,1088 912,1088 912,1197 964,1197 971,1204 971,1241 959,1253 912,1253
  region net VCC_5V: 871,1197 898,1197 898,1082 907,1073 1004,1073 1019,1088 1019,1254 996,1277 996,1396 997,1397 1090,1397 1098,1389 1098,1148 1084,1134 1084,1025 1067,1008 967,1008 960,1001 786,1001 786,1142 861,1142 871,1152
  region net GND: 940,2152 940,2040 939,2039 775,2039 775,2152
  region net GND: 370,1903 494,1903 503,1912 503,1941 508,1946 636,1946 636,1781 632,1777 380,1777 370,1787
  region net GND: 356,1730 337,1711 337,1550 341,1546 469,1546 475,1552 475,1614 489,1628 573,1628 573,1730
  pour cut-out: 545,2295 765,2295 765,2135 545,2135
  pour cut-out: 830,1780 955,1780 955,1630 830,1630
  pour cut-out: 840,1155 840,985 670,985 670,1155
  pour cut-out: 790,2745 790,2470 555,2470 555,2745
  pour cut-out: 2950,1555 3140,1555 3140,1390 2950,1390
  pour cut-out: 2830,2555 2845,2540 2845,1025 2790,970 1280,970 1245,1005 1245,2535 1265,2555
  pour cut-out: 580,1950 581.64,1951.64 770.24,1951.64 770.24,1777.23 771.61,1775.85 765.76,1770 573.05,1770 563.39,1779.66 563.39,1790.49 572,1799.1 572,1946 576,1950

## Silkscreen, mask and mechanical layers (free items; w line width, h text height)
Top Overlay:
  drawing of 5587 lines, arcs and shapes, not listed
  text "1" at 2624.43,3019.36 h30
  text "50" at 1562.03,3008.93 h30
  text "LCD RGB" at 2023,2955 h40
  text "K4" at 445,2920 h40
  text "K3" at 839,2920 h40
  text "K2" at 3321,2920 h40
  text "K1" at 3721,2920 h40
  text "RS485-3" at 3855,2883 h40
  text "AUDIO" at 165,2768 h40
  text "RS485-2" at 3855,2471 h40
  text "USB TYPE-A" at 88,2303 h40
  text "DC-IN" at 173,1653 h40
  text "GigibitEthernet" at 3810,1225 h40
  text "100ASK-T113-i_Industrial-DevKit V10" at 1685,770 h65
  text "CAN0" at 3810,754 h40
  text "SWITCH" at 228,504 h40
  text "RESET" at 2910,360 h40
  text "FEL" at 3544,358 h40
  text "CAN1" at 3810,348 h40
  text "TF Card" at 560,190 h40 r90
  text "USB OTG" at 1486,190 h40 r90
  text "USB DEBUG" at 2098,190 h40 r90
Bottom Overlay:
  lines w6: 1100,2660 1745,2660 3100,2660 ; 1100,2450 1110,2440 3100,2440 3100,2450 3100,2875 1100,2875 1100,2450
  text "EXPAND IO" at 1057,3051 h30
  text "5V" at 2940,2815 h30 r270
  text "5V" at 3035,2815 h30 r270
  text "GND" at 1440,2790 h30 r270
  text "GND" at 1640,2790 h30 r270
  text "GND" at 2140,2790 h30 r270
  text "GND" at 2445,2790 h30 r270
  text "GND" at 2840,2790 h30 r270
  text "TVIN0" at 1140,2765 h30 r270
  text "TVIN1" at 1235,2765 h30 r270
  text "HCEC" at 2240,2765 h30 r270
  text "HSCL" at 2345,2765 h30 r270
  text "FMINR" at 1840,2760 h30 r270
  text "FMINL" at 1940,2760 h30 r270
  text "HTX2P" at 2540,2740 h30 r270
  text "HTX1P" at 2640,2740 h30 r270
  text "HTX0N" at 2745,2740 h30 r270
  text "MICIN2N" at 1340,2715 h30 r270
  text "GPADC1" at 1540,2715 h30 r270
  text "MINCIN1P" at 2040,2695 h30 r270
  text "LINEOUTLP" at 1740,2670 h30 r270
  text "GND" at 1140,2575 h30 r270
  text "GND" at 1840,2575 h30 r270
  text "GND" at 2645,2570 h30 r270
  text "3.3V" at 2235,2565 h30 r270
  text "3.3V" at 3035,2565 h30 r270
  text "HSDA" at 2345,2550 h30 r270
  text "HHPD" at 2142.49,2545 h30 r270
  text "MBIAS" at 1335,2530 h30 r270
  text "LRADC" at 1440,2525 h30 r270
  text "HTX0P" at 2745,2525 h30 r270
  text "HTXCP" at 2840,2525 h30 r270
  text "HTX2N" at 2450,2520 h30 r270
  text "HTX1N" at 2540,2520 h30 r270
  text "HTXCN" at 2940,2520 h30 r270
  text "MICIN2P" at 1235,2500 h30 r270
  text "TVOUT0" at 2040,2500 h30 r270
  text "MINCIN1N" at 1940,2480 h30 r270
  text "LINEOUTLN" at 1740,2455 h30 r270
  text "LINEOUTRP" at 1540,2450 h30 r270
  text "LINEOUTRN" at 1635,2450 h30 r270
